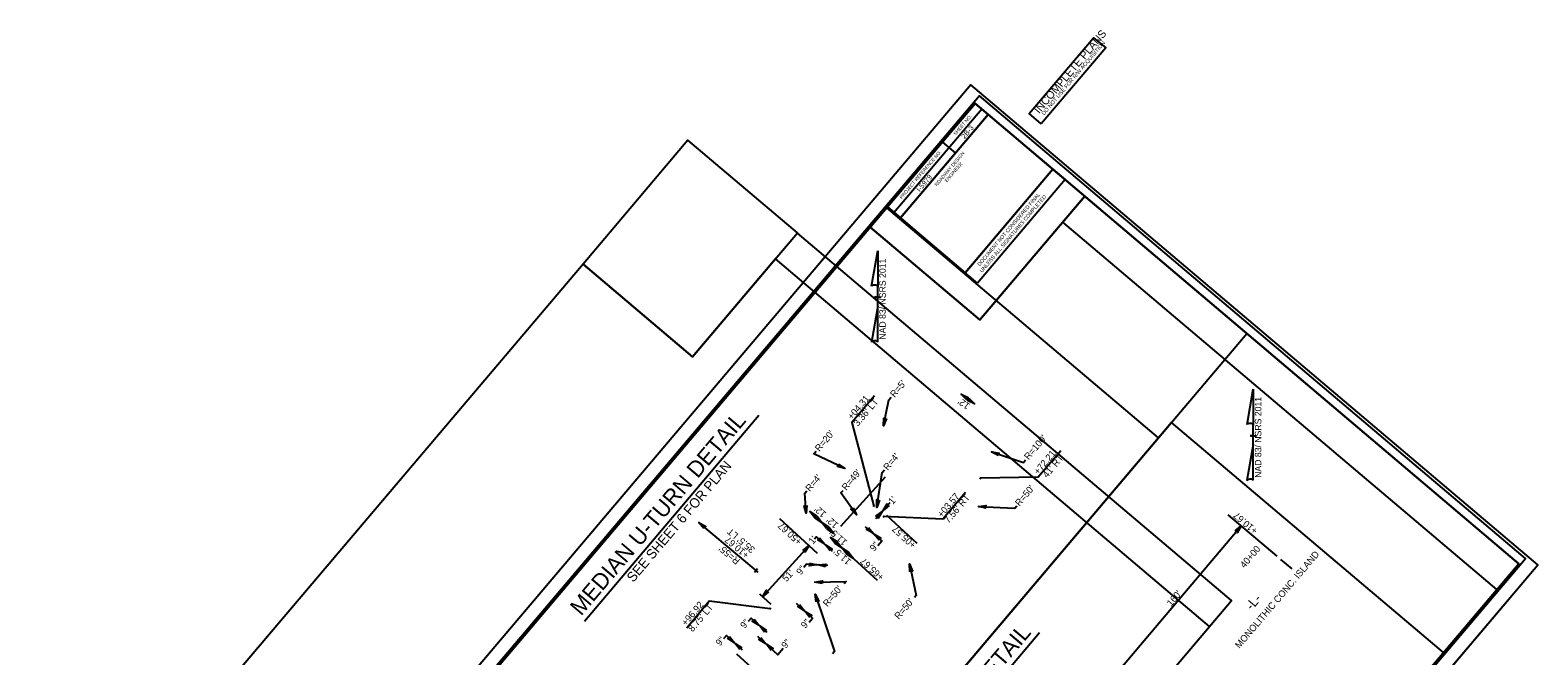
# Model space of a CAD drawing. Extents: x 1763138 to 1764249, y 424045 to 425159.
# Drawn here: x 1763138 to 1764249, y 424697 to 425159 of the extents above; entities that cross this region are included whole.
import ezdxf

# ---------------------------------------------------------------- set-up
doc = ezdxf.new("R2010")
doc.units = 0
for name, color, linetype in [('Default', 7, 'Continuous'), ('Matchline', 7, 'Continuous'), ('Old_Level_11', 7, 'Continuous'), ('Prop Dimension Text', 7, 'Continuous'), ('Prop Grid Mask', 7, 'Continuous'), ('Scratch_Level_0', 7, 'Continuous'), ('Sheet Block Revision CELL', 7, 'Continuous'), ('Sheet Clip Boundary CELL', 7, 'Continuous'), ('Sheet Cutting Line CELL', 7, 'Continuous'), ('Sheet Data Field CELL', 7, 'Continuous'), ('Sheet Layout Plan Border', 7, 'Continuous'), ('Sheet Plan Layout CELL', 7, 'Continuous'), ('Sheet Plot Border Inside CELL', 7, 'Continuous'), ('Sheet Plot Border Outside CELL', 7, 'Continuous'), ('Sheet Sticker Exception Certification CELL', 7, 'Continuous'), ('Sheet Sticker Incomplete CELL', 7, 'Continuous'), ('Sheet Title CELL', 7, 'Continuous')]:
    doc.layers.add(name, color=color, linetype=linetype)

# ---------------------------------------------------------------- blocks, each defined once
blk = doc.blocks.new('Terminator')
at = {"layer": 'Old_Level_11'}
blk.add_lwpolyline([(-9, 1.55), (0, 0), (-9.05, -1.6), (-7.9, 0)], close=True, dxfattribs=at)

msp = doc.modelspace()

# ---------------------------------------------------------------- linework, layer by layer
at = {"layer": 'Default'}
for p, q in [((1763672.2, 424760.4), (1763671.1, 424761.4)), ((1763673.9, 424759), (1763672.2, 424760.4))]:
    msp.add_line(p, q, dxfattribs=at)
at = {"layer": 'Matchline'}
for p, q in [((1763757.6, 424969.8), (1763762.2, 424995.9)), ((1763762.2, 424995.9), (1763762.2, 424995.9)), ((1763762.2, 424995.9), (1763762.2, 424995.9)), ((1763762.2, 424995.9), (1763762.2, 424969)), ((1763762.2, 424955), (1763762.2, 424969.8)), ((1763762.2, 424969), (1763762.2, 424969.7)), ((1763762.2, 424955), (1763757.5, 424928.5)), ((1763760, 424961.6), (1763759.9, 424961.6)), ((1763760, 424961.6), (1763764.5, 424961.6)), ((1763762, 424961.6), (1763760, 424961.6)), ((1763762.2, 424928.6), (1763762.2, 424955)), ((1764034.4, 424867.9), (1764039, 424894)), ((1764039, 424894), (1764039, 424894)), ((1764039, 424894), (1764039, 424894)), ((1764039, 424894), (1764039, 424867.1)), ((1764039, 424853.1), (1764039, 424867.9)), ((1764039, 424867.1), (1764039, 424867.8)), ((1764036.8, 424859.6), (1764036.7, 424859.6)), ((1764036.8, 424859.6), (1764041.3, 424859.6)), ((1764038.8, 424859.6), (1764036.8, 424859.6)), ((1764039, 424853.1), (1764034.3, 424826.5)), ((1764039, 424826.7), (1764039, 424853.1))]:
    msp.add_line(p, q, dxfattribs=at)
for centre, start_param, end_param in [((1763759.9, 424969.5), 0.216388, 2.908219), ((1763759.9, 424928.4), 0.201328, 3.141593), ((1764036.7, 424867.6), 0.216388, 2.908219), ((1764036.7, 424826.4), 0.201328, 3.141593)]:
    msp.add_ellipse(centre, major_axis=(2.38, -0.02), ratio=0.461098, start_param=start_param, end_param=end_param, dxfattribs=at)
at = {"layer": 'Old_Level_11'}
for points in [[(1763760.9, 424800.3), (1763765.5, 424803.8), (1763762.4, 424798.9), (1763762.1, 424800.1)], [(1763755.3, 424791.9), (1763759, 424787.4), (1763754, 424790.4), (1763755.2, 424790.7)], [(1763727.2, 424774.6), (1763723.6, 424779.1), (1763728.5, 424776), (1763727.3, 424775.8)], [(1763730.8, 424780.1), (1763727.3, 424784.6), (1763732.2, 424781.5), (1763731, 424781.3)], [(1763732.3, 424781.4), (1763735.8, 424776.9), (1763730.9, 424780), (1763732.1, 424780.2)], [(1763739.3, 424772.3), (1763735.8, 424776.9), (1763740.7, 424773.8), (1763739.5, 424773.5)], [(1763763.2, 424782.5), (1763759.5, 424786.9), (1763764.5, 424784), (1763763.3, 424783.7)], [(1763740.7, 424773.7), (1763744.3, 424769.1), (1763739.4, 424772.2), (1763740.6, 424772.5)], [(1763723.8, 424763), (1763718.2, 424764.3), (1763723.9, 424765), (1763723.2, 424764)], [(1763721.6, 424750.7), (1763715.9, 424751.5), (1763721.6, 424752.7), (1763720.9, 424751.7)], [(1763704.6, 424735.1), (1763708.1, 424730.6), (1763703.2, 424733.7), (1763704.4, 424733.9)], [(1763716.8, 424737.1), (1763716, 424742.8), (1763718.7, 424737.7), (1763717.5, 424738.1)], [(1763671.1, 424724.4), (1763674.6, 424719.8), (1763669.7, 424722.9), (1763670.9, 424723.2)], [(1763712.2, 424725.5), (1763708.7, 424730.1), (1763713.6, 424727), (1763712.3, 424726.7)], [(1763678.7, 424714.8), (1763675.2, 424719.3), (1763680, 424716.2), (1763678.8, 424716)], [(1763660.6, 424702), (1763657, 424706.5), (1763661.9, 424703.4), (1763660.7, 424703.1)], [(1763683.6, 424701.3), (1763680.1, 424705.8), (1763685, 424702.7), (1763683.8, 424702.5)]]:
    msp.add_lwpolyline(points, close=True, dxfattribs=at)
at = {"layer": 'Prop Grid Mask'}
for p, q in [((1763546, 424722.9), (1763674.6, 424874.7)), ((1763738.8, 424546.2), (1763881.3, 424714.4))]:
    msp.add_line(p, q, dxfattribs=at)
at = {"layer": 'Sheet Block Revision CELL'}
for points in [[(1763766, 424212), (1764218.4, 424746.1), (1763898.5, 425017.1), (1763837.4, 424944.9), (1763756.7, 425013.3), (1763365.4, 424551.4)], [(1763554.3, 424184.9), (1764006.7, 424719), (1763686.8, 424990), (1763625.7, 424917.8), (1763545, 424986.1), (1763153.7, 424524.2)]]:
    msp.add_lwpolyline(points, close=True, dxfattribs=at)
at = {"layer": 'Sheet Clip Boundary CELL'}
for p, q in [((1763830.9, 425118.3), (1763286.8, 424476)), ((1763704.6, 424122.1), (1764248.7, 424764.4))]:
    msp.add_line(p, q, dxfattribs=at)
at = {"layer": 'Sheet Cutting Line CELL'}
for points in [[(1763837.4, 424944.9), (1763914.7, 425036.2), (1763834, 425104.6), (1763756.7, 425013.3)], [(1763625.7, 424917.8), (1763703, 425009.1), (1763622.3, 425077.4), (1763545, 424986.1)], [(1763349.2, 424532.3), (1763749.8, 424192.9), (1764234.6, 424765.2), (1763914.7, 425036.2), (1763837.4, 424944.9), (1763756.7, 425013.3)], [(1763137.5, 424505.1), (1763538.1, 424165.8), (1764022.9, 424738), (1763703, 425009), (1763625.7, 424917.8), (1763545, 424986.1)]]:
    msp.add_lwpolyline(points, close=True, dxfattribs=at)
at = {"layer": 'Sheet Data Field CELL'}
for p, q in [((1763774.1, 425024.2), (1763838.8, 425100.5)), ((1763809.8, 425075.9), (1763819.4, 425067.8))]:
    msp.add_line(p, q, dxfattribs=at)
for points in [[(1763834, 425104.5), (1763349.2, 424532.3), (1763749.8, 424192.9), (1764234.6, 424765.2)], [(1763769.4, 425028.2), (1763834, 425104.5), (1763843.6, 425096.4), (1763778.9, 425020.1)], [(1763778.9, 425020.1), (1763843.6, 425096.4), (1763891.3, 425056.1), (1763826.6, 424979.7)], [(1763749.8, 424192.9), (1763349.2, 424532.3), (1763769.4, 425028.2), (1763826.6, 424979.7), (1763891.3, 425056), (1764234.6, 424765.2)]]:
    msp.add_lwpolyline(points, close=True, dxfattribs=at)
at = {"layer": 'Sheet Layout Plan Border'}
msp.add_line((1763735, 424793), (1763768, 424829.2), dxfattribs=at)
at = {"layer": 'Sheet Plan Layout CELL'}
msp.add_lwpolyline([(1763701.2, 424133.6), (1764239.6, 424769.1), (1763837.1, 425110.1), (1763298.7, 424474.5)], close=True, dxfattribs=at)
at = {"layer": 'Sheet Plot Border Inside CELL'}
msp.add_lwpolyline([(1763704.6, 424122.1), (1764248.7, 424764.4), (1763830.9, 425118.3), (1763286.8, 424476)], close=True, dxfattribs=at)
at = {"layer": 'Sheet Sticker Exception Certification CELL'}
for p, q in [((1763826.6, 424979.7), (1763891.3, 425056)), ((1763826.6, 424979.7), (1763891.3, 425056)), ((1763891.3, 425056), (1763900.2, 425048.4)), ((1763891.3, 425056), (1763900.2, 425048.4)), ((1763900.2, 425048.4), (1763835.6, 424972.1)), ((1763900.2, 425048.4), (1763835.6, 424972.1)), ((1763835.6, 424972.1), (1763826.6, 424979.7)), ((1763835.6, 424972.1), (1763826.6, 424979.7))]:
    msp.add_line(p, q, dxfattribs=at)
for points in [[(1763589.5, 424409.8), (1763969.1, 424857.9), (1763768.8, 425027.6), (1763389.3, 424579.5)], [(1763789.8, 424240.2), (1764179.1, 424699.7), (1763978.8, 424869.3), (1763589.5, 424409.8)]]:
    msp.add_lwpolyline(points, close=True, dxfattribs=at)
at = {"layer": 'Sheet Sticker Incomplete CELL'}
msp.add_lwpolyline([(1763882.6, 425089.4), (1763873.7, 425097), (1763921.2, 425153), (1763930.2, 425145.4)], close=True, dxfattribs=at)
at = {"layer": 'Sheet Title CELL'}
for p, q in [((1763549.5, 424362.6), (1764034.3, 424934.9)), ((1763823.7, 424890.1), (1763833.5, 424883.1)), ((1763838.4, 424827.9), (1763837.5, 424828.6)), ((1763838.3, 424828.6), (1763837.6, 424827.8)), ((1763712.2, 424803.6), (1763729.9, 424787.5)), ((1763759.8, 424807.3), (1763758.9, 424808)), ((1763759.7, 424808.1), (1763759, 424807.3)), ((1763767.2, 424799.6), (1763766.3, 424800.3)), ((1763767.1, 424800.3), (1763766.4, 424799.5)), ((1763791.3, 424780.2), (1763768.8, 424800.8)), ((1764056.5, 424770.7), (1764020.5, 424801.2)), ((1763672.5, 424760.2), (1763630.4, 424795.6)), ((1763689.9, 424798.5), (1763717.6, 424773.1)), ((1763926.7, 424671), (1764030.1, 424793.1)), ((1763677.2, 424740.9), (1763711.6, 424778.6)), ((1763727.3, 424784.6), (1763744.3, 424769.1)), ((1763762.1, 424752.8), (1763744.9, 424768.6)), ((1764067.5, 424761.4), (1764059.3, 424768.3)), ((1763671.1, 424761.4), (1763673.9, 424759)), ((1763673.6, 424761.4), (1763671.3, 424758.7)), ((1763675, 424743), (1763683.4, 424735.3)), ((1763683.4, 424731.6), (1763682.5, 424732.3)), ((1763683.3, 424732.4), (1763682.6, 424731.6)), ((1763658.1, 424698.8), (1763685.6, 424673.8))]:
    msp.add_line(p, q, dxfattribs=at)
for points in [[(1763759.8, 424889), (1763743.2, 424869.3), (1763759.3, 424807.7)], [(1763766.5, 424866.8), (1763770.4, 424886), (1763772.1, 424888)], [(1763738, 424835.4), (1763715.2, 424846.1), (1763716.8, 424848.1)], [(1763897.1, 424848.5), (1763880.4, 424828.9), (1763838, 424828.2)], [(1763846, 424847.7), (1763869.5, 424839.8), (1763871.2, 424841.7)], [(1763761.6, 424806.7), (1763765.5, 424832.4), (1763767.2, 424834.4)], [(1763709.5, 424802.4), (1763708.4, 424817.1), (1763710, 424819)], [(1763746.6, 424801.3), (1763735, 424817.4), (1763736.6, 424819.3)], [(1763760.7, 424798.6), (1763771.4, 424810.3)], [(1763826.8, 424817.7), (1763810.1, 424798.1), (1763766.7, 424799.9)], [(1763836.4, 424807.5), (1763863.2, 424806.1), (1763864.8, 424808)], [(1763762.2, 424778.7), (1763765.1, 424782.2), (1763753.1, 424792.5)], [(1763728.9, 424774.3), (1763717.1, 424785), (1763715.7, 424783.3)], [(1763725.5, 424763.9), (1763709.7, 424764.8), (1763707.7, 424762.4)], [(1763785.5, 424765.1), (1763790.6, 424741.8), (1763789.3, 424740.4)], [(1763715.9, 424751.5), (1763738.9, 424752.2), (1763737.4, 424750.3)], [(1763683, 424732), (1763638, 424737.5), (1763621.4, 424717.8)], [(1763711.6, 424722.2), (1763714.1, 424725.1), (1763702.4, 424735.8)], [(1763716, 424742.8), (1763730.2, 424700.4), (1763728.9, 424698.9)], [(1763680.6, 424714.4), (1763668.8, 424725.1), (1763666.8, 424722.6)], [(1763662.5, 424701.6), (1763650.7, 424712.2), (1763648.6, 424709.8)], [(1763692.5, 424702.7), (1763688.6, 424698), (1763673.8, 424711.5)]]:
    msp.add_lwpolyline(points, dxfattribs=at)

# ---------------------------------------------------------------- block references
at = {"layer": 'Default'}
for p, xscale, yscale, rotation in [((1763823.7, 424890.1), 0.6300000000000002, 0.6299999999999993, 144.67631357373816), ((1763833.5, 424883.1), 0.6300000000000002, 0.6299999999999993, -35.32368642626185), ((1763766.5, 424866.8), 0.6300000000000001, 0.6299999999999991, -101.50529000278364), ((1763846, 424847.7), 0.6300000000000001, 0.6299999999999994, 160.28086988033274), ((1763738, 424835.4), 0.6300000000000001, 0.6299999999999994, -25.140135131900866), ((1763761.6, 424806.7), 0.6300000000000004, 0.6299999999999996, -98.78922434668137), ((1763709.5, 424802.4), 0.6300000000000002, 0.6299999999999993, -85.4688820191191), ((1763712.2, 424803.6), 0.6300000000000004, 0.6299999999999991, 137.61701176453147), ((1763721, 424795.6), 0.6300000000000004, 0.6299999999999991, -42.38298823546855), ((1763746.6, 424801.3), 0.6300000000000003, 0.6299999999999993, -54.284425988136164), ((1763766.1, 424804.5), 0.6300000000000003, 0.6299999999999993, -132.29820067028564), ((1763836.4, 424807.5), 0.6300000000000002, 0.6299999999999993, 176.8941479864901), ((1763630.4, 424795.6), 0.6300000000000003, 0.6299999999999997, 139.87464985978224), ((1763721, 424795.6), 0.6300000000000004, 0.6299999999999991, 137.61701176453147), ((1763729.9, 424787.5), 0.6300000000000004, 0.6299999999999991, -42.38298823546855), ((1764030.1, 424793.1), 0.6300000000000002, 0.6299999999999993, 49.73010343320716), ((1763711.6, 424778.6), 0.6300000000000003, 0.6299999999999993, 47.61701176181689), ((1763722.9, 424779.8), 0.6300000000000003, 0.6299999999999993, -42.29820066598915), ((1763717.4, 424764.3), 0.6300000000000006, 0.6299999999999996, -3.143469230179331), ((1763785.5, 424765.1), 0.6300000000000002, 0.6299999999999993, 102.29897037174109), ((1763677.2, 424740.9), 0.6300000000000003, 0.6299999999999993, -132.38298823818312), ((1763656.5, 424707), 0.6300000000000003, 0.6299999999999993, -42.29820066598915), ((1763679.5, 424706.3), 0.6300000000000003, 0.6299999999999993, -42.29820066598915)]:
    msp.add_blockref('Terminator', p, dxfattribs=dict(at, xscale=xscale, yscale=yscale, rotation=rotation))

# ---------------------------------------------------------------- texts
at = {"layer": 'Matchline'}
for p in [(1763768.1, 424930.4), (1764044.9, 424828.5)]:
    msp.add_text('NAD 83/ NSRS 2011', height=4.781, rotation=90, dxfattribs=at).set_placement(p)
at = {"layer": 'Prop Dimension Text'}
for s, height, rotation, p in [("R=5'", 5, 49.7301, (1763774.6, 424887.4)), ('+04.31', 5, 49.7301, (1763743.2, 424871)), ("3.36' LT", 5, 49.7301, (1763747.6, 424866.1)), ("12'", 5, 144.6763, (1763830.6, 424882.6)), ('MEDIAN U-TURN DETAIL', 12, 49.7301, (1763543.6, 424726.2)), ("R=20'", 5, 49.7301, (1763719.2, 424847.5)), ("R=100'", 5, 49.7301, (1763873.4, 424841.4)), ("R=4'", 5, 49.7301, (1763769.6, 424833.6)), ('+72.21', 5, 49.7301, (1763880.5, 424830.5)), ("41' RT", 5, 49.7301, (1763887, 424828.1)), ('SEE SHEET 6 FOR PLAN', 7.2, 49.7301, (1763582, 424751)), ("R=49'", 5, 49.7301, (1763739, 424818.8)), ("R=4'", 5, 49.7301, (1763712.2, 424818)), ("R=50'", 5, 49.7301, (1763866.7, 424807.2)), ("1'", 5, 49.7301, (1763773.3, 424808.5)), ('+03.57', 5, 49.7301, (1763809.5, 424798.9)), ("7.56' RT", 5, 49.7301, (1763814.4, 424794.6)), ("12'", 5, 137.617, (1763724.7, 424802.5)), ("12'", 5, 137.617, (1763733.6, 424794.4)), ('+10.67', 5, 139.7301, (1764042.7, 424790.3)), ("35.5' LT", 5, 139.8746, (1763672.2, 424776.4)), ('+50.67', 5, 137.617, (1763706.7, 424782.2)), ("11.5'", 5, 137.617, (1763740.1, 424781.7)), ('+05.57', 5, 137.617, (1763790.9, 424779.7)), ("R=55'", 5, 139.8746, (1763661.1, 424768)), ('+10.67', 5, 139.8746, (1763667.9, 424772.4)), ("1'", 5, 49.7301, (1763714.5, 424779.2)), ('9"', 5, 49.7301, (1763759.6, 424774)), ("11.5'", 5, 137.617, (1763743, 424767.5)), ('+65.67', 5, 137.617, (1763767.3, 424756)), ('MONOLITHIC CONC. ISLAND', 5, 49.6025, (1764028.8, 424702.4)), ("51'", 5, 47.617, (1763694.9, 424751.5)), ('9"', 5, 49.7301, (1763705.4, 424756.5)), ("R=50'", 5, 49.7301, (1763725.1, 424733.1)), ("160'", 5, 49.7301, (1763978.5, 424733.4)), ('+96.92', 5, 49.7301, (1763620.9, 424719)), ("8.75' LT", 5, 49.7301, (1763625.8, 424714.6)), ("R=50'", 5, 49.7301, (1763777.8, 424723.8)), ('9"', 5, 49.7301, (1763664.1, 424717)), ('9"', 5, 49.7301, (1763708.8, 424717.1)), ('9"', 5, 49.7301, (1763646, 424704.2)), ('9"', 5, 49.7301, (1763694.4, 424702.3)), ('MEDIAN LEFT TURN DETAIL', 12, 49.7301, (1763736.4, 424549.5))]:
    msp.add_text(s, height=height, rotation=rotation, dxfattribs=at).set_placement(p)
at = {"layer": 'Scratch_Level_0'}
for s, height, p in [('40+00', 5, (1764032.5, 424761.6)), ('-L-', 7, (1764037.9, 424730.4))]:
    msp.add_text(s, height=height, rotation=49.7301, dxfattribs=at).set_placement(p)
at = {"layer": 'Sheet Data Field CELL'}
for s, p in [('SHEET NO.', (1763819.7, 425080.8)), ('PROJECT REFERENCE NO.', (1763779.9, 425033.9)), ('ROADWAY DESIGN', (1763805.7, 425043.2)), ('ENGINEER', (1763813.2, 425046.2))]:
    msp.add_text(s, height=2.5, rotation=49.7301, dxfattribs=at).set_placement(p)
at = {"layer": 'Sheet Plot Border Outside CELL'}
for s, p in [('2B-3', (1763826.2, 425078.1)), ('I-5979', (1763793.1, 425039))]:
    msp.add_text(s, height=3.75, rotation=49.7301, dxfattribs=at).set_placement(p)
at = {"layer": 'Sheet Sticker Exception Certification CELL'}
for s, p in [('DOCUMENT NOT CONSIDERED FINAL', (1763837.4, 424984.4)), ('DOCUMENT NOT CONSIDERED FINAL', (1763837.4, 424984.4)), ('UNLESS ALL SIGNATURES COMPLETED', (1763839.1, 424979.6)), ('UNLESS ALL SIGNATURES COMPLETED', (1763839.1, 424979.6))]:
    msp.add_text(s, height=2.75, rotation=49.7301, dxfattribs=at).set_placement(p)
at = {"layer": 'Sheet Sticker Incomplete CELL'}
for s, height, p in [('INCOMPLETE PLANS', 5.76, (1763881.1, 425096.6)), ('DO NOT USE FOR R/W ACQUISITION', 2.88, (1763884.8, 425095.6))]:
    msp.add_text(s, height=height, rotation=49.7301, dxfattribs=at).set_placement(p)

doc.saveas('drawing.dxf')
